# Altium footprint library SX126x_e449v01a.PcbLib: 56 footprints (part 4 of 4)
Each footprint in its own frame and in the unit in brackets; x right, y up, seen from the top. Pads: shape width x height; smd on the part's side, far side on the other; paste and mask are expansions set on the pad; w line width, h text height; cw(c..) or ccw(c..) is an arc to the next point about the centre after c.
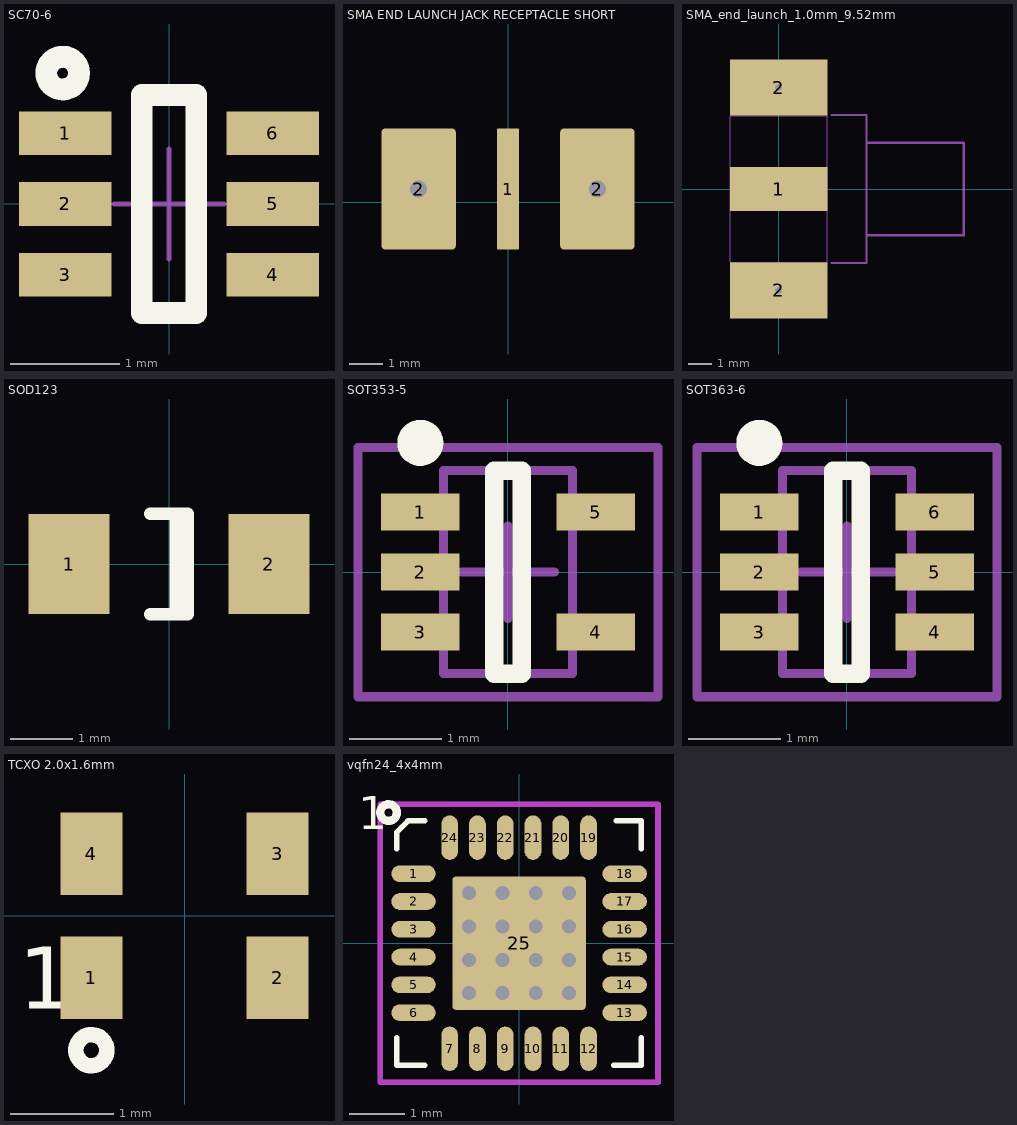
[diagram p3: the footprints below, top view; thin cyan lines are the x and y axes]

## SC70-6 [mm] "SC70 6-Leads, Body 2.0x1.25mm, Pitch 0.65mm"
height 1.45
pads (6):
  rect 0.85x0.4 smd mask+0.05: 1(-0.95,0.65) 2(-0.95,0) 3(-0.95,-0.65) 4(0.95,-0.65) 5(0.95,0) 6(0.95,0.65)
Top Overlay:
  circle w0.2: c-0.975,1.2 r0.15
  lines w0.2: -0.25,-1 0.25,-1 0.25,1 -0.25,1 -0.25,-1
Mechanical 15:
  lines w0.05: -0.5,0 0.5,0 ; 0,-0.5 0,0.5
3D body: height 1.45, standoff 0, extent -0.625,-1 0.625,1

## SMA END LAUNCH JACK RECEPTACLE SHORT [mm] "SMA Connector - End Launch Jack Receptacle - Short"
height 8
pads (3):
  rrect10% 0.65x3.6 smd paste+0 mask+0.05: 1(0,0.4)
  rrect10% 2.2x3.6 hole 0.5 mask+0.1: 2(-2.65,0.4) 2(2.65,0.4)
3D body: height 2.95, standoff 0, extent -0.325,-0.4 0.325,0.4

## SMA_end_launch_1.0mm_9.52mm [mm] "SMA end launch for 1.0mm PCB thickness; 9.52mm"
height 10
pads (3):
  rect 4.2x1.905 smd mask+0.05: 1(0,0)
  rect 4.2x2.413 hole 0.3 mask+0.05: 2(0,-4.38) 2(0,4.38)
Mechanical 15:
  lines w0.01: -2.1,-3.17 -2.1,3.17 2.1,3.17 2.1,-3.17 -2.1,-3.17
  lines w0.1: 2.295,-3.2 3.796,-3.2 3.796,-2 ; 2.295,3.2 3.796,3.2 3.796,2 ; 3.796,-2 3.796,2 ; 3.796,-2 8,-2 8,2 3.796,2

## SOD123 [mm] "SOD123; Chip Diode; Body  2.7 x 1.6 mm (LxW typ)"
height 1.35
pads (2):
  rect 1.3x1.6 smd mask+0.05: 1(-1.6,0) 2(1.6,0)
Top Overlay:
  lines w0.2: -0.3,-0.8 0.3,-0.8 0.3,0.8 -0.3,0.8 ; 0.11,-0.8 0.11,0.8

## SOT353-5 [mm] "SOT353, 5-Leads, Body 2x1.3mm, Pitch 0.65mm, Lead Span 2.1mm, IPC Medium Density"
height 1.1
pads (5):
  rect 0.85x0.4 smd mask+0.05: 1(-0.95,0.65) 2(-0.95,0) 3(-0.95,-0.65) 4(0.95,-0.65) 5(0.95,0.65)
Top Overlay:
  circle w0.25: c-0.95,1.4 r0.125
  lines w0.2: -0.15,-1.1 -0.15,1.1 0.15,1.1 0.15,-1.1 -0.15,-1.1
Mechanical 13:
  lines w0.1: -0.7,-1.1 0.7,-1.1 0.7,1.1 -0.7,1.1 -0.7,-1.1
Mechanical 15:
  lines w0.1: -0.5,0 0.5,0 ; 0,-0.5 0,0.5 ; -1.625,-1.35 1.625,-1.35 1.625,1.35 -1.625,1.35 -1.625,-1.35
3D body: height 1.1, standoff 0, extent -0.7,-1.1 0.7,1.1

## SOT363-6 [mm] "SOT363, 6-Leads, Body 2x1.3mm, Pitch 0.65mm, Lead Span 2.1mm, IPC Medium Density"
height 1
pads (6):
  rect 0.85x0.4 smd mask+0.05: 1(-0.95,0.65) 2(-0.95,0) 3(-0.95,-0.65) 4(0.95,-0.65) 5(0.95,0) 6(0.95,0.65)
Top Overlay:
  circle w0.25: c-0.95,1.4 r0.125
  lines w0.2: -0.15,-1.1 0.15,-1.1 0.15,1.1 -0.15,1.1 -0.15,-1.1
Mechanical 13:
  lines w0.1: -0.7,-1.1 -0.7,1.1 0.7,1.1 0.7,-1.1 -0.7,-1.1
Mechanical 15:
  lines w0.1: -0.5,0 0.5,0 ; 0,-0.5 0,0.5 ; -1.625,-1.35 -1.625,1.35 1.625,1.35 1.625,-1.35 -1.625,-1.35
3D body: height 1, standoff 0, extent -0.7,-1.1 0.7,1.1

## TCXO 2.0x1.6mm [mm] "SMD 2.0x1.6mm for TCXO or VCTCXO"
height 1
pads (4):
  rect 0.6x0.8 smd mask+0.05: 1(-0.9,-0.6) 2(0.9,-0.6) 3(0.9,0.6) 4(-0.9,0.6)
Top Overlay:
  circle w0.15: c-0.9,-1.3 r0.15
  text "1" at -1.6,-0.9 h0.6
3D body: height 1, standoff 0, extent -1,-0.8 1,0.8

## vqfn24_4x4mm [mm] "24 Leads, Body 4.0x4.0mm, Pitch 0.50mm, VQFN24"
height 1
pads (25):
  oval 0.8x0.3 smd mask+0.05: 1(-1.9,1.25) 2(-1.9,0.75) 3(-1.9,0.25) 4(-1.9,-0.25) 5(-1.9,-0.75) 6(-1.9,-1.25) 13(1.9,-1.25) 14(1.9,-0.75) 15(1.9,-0.25) 16(1.9,0.25) 17(1.9,0.75) 18(1.9,1.25)
  oval 0.3x0.8 smd mask+0.05: 7(-1.25,-1.9) 8(-0.75,-1.9) 9(-0.25,-1.9) 10(0.25,-1.9) 11(0.75,-1.9) 12(1.25,-1.9) 19(1.25,1.9) 20(0.75,1.9) 21(0.25,1.9) 22(-0.25,1.9) 23(-0.75,1.9) 24(-1.25,1.9)
  rrect5% 2.4x2.4 smd paste-2.5 mask+0.05: 25(0,0)
via 0.3,-0.3 diameter 0.5 hole 0.25
via 0.3,-0.9 diameter 0.5 hole 0.25
via 0.9,-0.9 diameter 0.5 hole 0.25
via 0.9,-0.3 diameter 0.5 hole 0.25
via 0.9,0.3 diameter 0.5 hole 0.25
via 0.9,0.9 diameter 0.5 hole 0.25
via 0.3,0.3 diameter 0.5 hole 0.25
via 0.3,0.9 diameter 0.5 hole 0.25
via -0.3,-0.9 diameter 0.5 hole 0.25
via -0.3,0.9 diameter 0.5 hole 0.25
via -0.3,-0.3 diameter 0.5 hole 0.25
via -0.9,0.9 diameter 0.5 hole 0.25
via -0.9,-0.3 diameter 0.5 hole 0.25
via -0.9,0.3 diameter 0.5 hole 0.25
via -0.9,-0.9 diameter 0.5 hole 0.25
via -0.3,0.3 diameter 0.5 hole 0.25
Top Overlay:
  circle w0.15: c-2.35,2.35 r0.15
  lines w0.1: -2.2,-1.7 -2.2,-2.2 -1.7,-2.2 ; -2.2,1.7 -2.2,2 -2,2.2 -1.7,2.2 ; 1.7,-2.2 2.2,-2.2 2.2,-1.7 ; 1.75,2.2 2.2,2.2 2.2,1.7
  text "1" at -2.9,2.05 h0.6
Top Paste:
  region: 0.05,-1.15 1.15,-1.15 1.15,-0.05 0.05,-0.05
  region: 0.05,0.05 1.15,0.05 1.15,1.15 0.05,1.15
  region: -1.15,0.05 -0.05,0.05 -0.05,1.15 -1.15,1.15
  region: -1.15,-1.15 -0.05,-1.15 -0.05,-0.05 -1.15,-0.05
Mechanical 15 keep-out:
  lines w0.1: -2.5,-2.5 -2.5,2.5 2.5,2.5 2.5,-2.5 -2.5,-2.5
3D body: height 1, standoff 0.05, extent -2,-2 2,2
